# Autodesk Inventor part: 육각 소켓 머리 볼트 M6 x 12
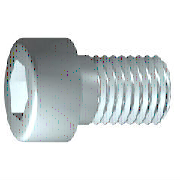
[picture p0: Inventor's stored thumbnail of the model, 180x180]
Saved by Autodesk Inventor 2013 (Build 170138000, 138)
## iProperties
IsCustomPart: 1
Created: 2012-02
Part Number: 육각 소켓 머리 볼트 M6 x 12
Material: 스테인리스강
Description: 6각 소켓 머리 캡 나사
Document SubType Name: Modeling
Standard: ISO 4762
Designer: mdu-01
Standard Revision: Fourth edition 2004-03-01
Standards Organization: ISO
Language: ko-KR
Size Designation: M6 x 12
Categories: <MemberInstance><Categories><Category DisplayName="조임쇠" InternalName="e4da775c-781d-43d5-af7c-5136215cf5a6" Mnemonic="FSTN"><Category DisplayName="볼트" InternalN
Density: 7.75 g/cm^3
Mass: 5.625 g
Surface Area: 6.13303 cm^2
Volume: 0.725807 cm^3
Author: mdu-01
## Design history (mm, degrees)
sketch "스케치1"
  geometry: L1 (-1.333, 0)-(12, 0); L2 (12, 0)-(12, 3); L3 (12, 3)-(2.5, 3); L4 (2.5, 3)-(1.886, 3); L5 (1.886, 3)-(0, 3); L6 (0, 3)-(0, 5); L7 (0, 5)-(-6, 5); L8 (-6, 5)-(-6, 2.887); L9 (-6, 2.887)-(-3, 2.887); L10 (-3, 2.887)-(-1.333, 0); L11 (-9.6, 0)-(15.6, 0) reference; L12 (0, -1)-(0, 6) reference; L13 (2.5, 3)-(0, 3)
  constraints: 22 end point, 6 parallel, 2 collinear, 2 perpendicular, 1 horizontal, 1 point on line
  dimensions: "d1" = 9.5 distance from line of L3.end L2 (= GEL); "d2" = 0.61355 distance of L4.end L3.end (computed from GAL); "d3" = 6 distance between parallel lines of L8 L6 (= KOH); "d4" = 3 distance of L8.end L9.end (= INTI); "d5" = 60 deg angle of L10 L1; "d6" = 6 diameter of L3 L1 (= GD); "d7" = 6 diameter of L5 L1 (= BDM); "d8" = 5.7735 diameter of L9 L1 (= 1.1547 x SW); "d9" = 10 diameter of L7 L1 (= KOD); "d26" = 12 distance between parallel lines of L12 L2 (= NLG)
revolve "본체" sketch "스케치1" stored, may be unused: angle "d10" = 90 deg
sketch "스케치2"
  geometry: L1 (0, -7)-(0, 7) reference; L2 (-7, 0)-(7, 0) reference; L3 (2.887, 0)-(1.443, -2.5); L4 (1.443, -2.5)-(-1.443, -2.5); L5 (-1.443, -2.5)-(-2.887, 0); L6 (-2.887, 0)-(-1.443, 2.5); L7 (-1.443, 2.5)-(1.443, 2.5); L8 (1.443, 2.5)-(2.887, 0); 2 further points
  constraints: 12 end point, 1 coincident, 1 horizontal alignment, 1 point on line, 12 other
extrude "슬롯" join sketch "스케치2" stored distance "d11" = 10; taper "d12" = 0 deg
workplane "Work Plane1"
fillet "Fillet2" dims "d30" = 0.05 (= R)
body "Solid1"
fillet "모깎기1" dims "d17" = 0.6 (= RR)
feature "스레드" dims "d13" = 9.5 (= GEL), "d14" = 0
chamfer "모따기1" distance "d15" = 0.61345 (= -0.5 x SPD + 0.5 x GD); stored, may be unused: second distance "d16" = 0.61345 (= GUL), angle "d27" = 45 deg
other parameters: "GD" = 6 [user parameter; used in 2 equation terms], "NLG" = 12 [user parameter; used in 1 equation term], "GEL" = 9.5 [user parameter; used in 2 equation terms], "KOD" = 10 [user parameter; used in 1 equation term], "KOH" = 6 [user parameter; used in 1 equation term], "INTI" = 3 [user parameter; used in 1 equation term], "GAL" = 0.61345 (= 0.61345 x PTC) [user parameter; used in 1 equation term], "GUL" = 0.61345 (= 0.61345 x PTC) [user parameter; used in 1 equation term], "BDM" = 6 (= NND) [user parameter; used in 1 equation term], "SW" = 5 [user parameter; used in 2 equation terms], "RR" = 0.6 [user parameter; used in 1 equation term], "SPD" = 4.7731 (= NND - 1.2269 x PTC) [user parameter; used in 1 equation term], "d19" = 0, "d28" = 0, "d29" = 0, "R" = 0.05 [user parameter; used in 1 equation term], "TOA" = 30 deg [user parameter], "GD1" = 4.7731 (= THREADDIA - 1.2269 x PTC) [user parameter], "THREADDIA" = 6 [user parameter; used in 1 equation term], "FAWI" = 45 deg [user parameter], "PTC" = 1 [user parameter; used in 5 equation terms], "NND" = 6 [user parameter; used in 2 equation terms], "E0" = 5.775 (= 1.155 x SW) [user parameter]
